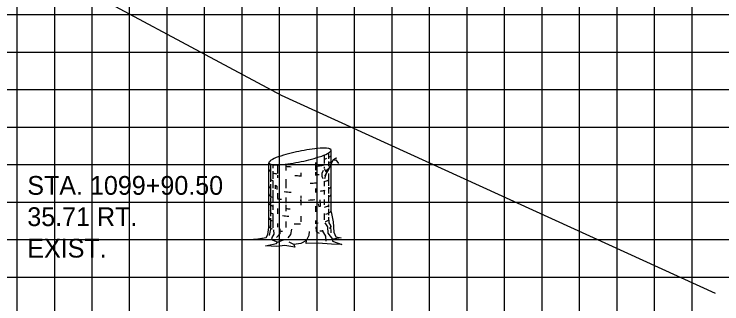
# Model space of a CAD drawing. Extents: x 1076304 to 1076474, y 779716 to 779826.
# Drawn here: x 1076415.71 to 1076434.59, y 779767.99 to 779775.71 of the extents above; entities that cross this region are included whole.
import ezdxf

# ---------------------------------------------------------------- set-up
doc = ezdxf.new("R2010")
doc.units = 0
for name, color, linetype in [('D_Text_Monospaced', 7, 'Continuous'), ('M_Trees_Conifer_Pay', 7, 'Continuous'), ('MAJOR', 7, 'Continuous'), ('MINOR', 7, 'Continuous'), ('S_Roadway_Centerline', 7, 'Continuous'), ('S_Trees_Decid_Pay', 7, 'Continuous')]:
    doc.layers.add(name, color=color, linetype=linetype)

msp = doc.modelspace()

# ---------------------------------------------------------------- linework, layer by layer
at = {"layer": 'M_Trees_Conifer_Pay'}
for p, q in [((1076424.171, 779770.443), (1076424.171, 779772.09)), ((1076423.982, 779771.957), (1076423.982, 779771.733)), ((1076424.099, 779772.018), (1076424.099, 779771.855)), ((1076422.507, 779770.033), (1076422.507, 779771.754)), ((1076422.554, 779771.717), (1076422.554, 779771.246)), ((1076422.613, 779771.706), (1076422.613, 779771.608)), ((1076422.958, 779771.718), (1076422.958, 779771.55)), ((1076423.754, 779771.76), (1076423.754, 779771.561)), ((1076424.099, 779771.787), (1076424.099, 779771.659)), ((1076422.613, 779771.534), (1076422.613, 779771.33)), ((1076422.738, 779771.698), (1076422.738, 779771.466)), ((1076423.982, 779771.645), (1076423.982, 779771.598)), ((1076422.738, 779771.425), (1076422.738, 779771.351)), ((1076423.363, 779771.487), (1076423.363, 779771.392)), ((1076423.754, 779771.503), (1076423.754, 779771.415)), ((1076424.039, 779771.462), (1076423.988, 779771.402)), ((1076424.099, 779771.472), (1076424.099, 779771.136)), ((1076422.554, 779771.182), (1076422.554, 779770.873)), ((1076422.613, 779771.272), (1076422.613, 779771.073)), ((1076422.958, 779771.314), (1076422.958, 779771.077)), ((1076423.982, 779771.262), (1076423.982, 779771.13)), ((1076422.613, 779771.025), (1076422.613, 779770.69)), ((1076423.754, 779771.067), (1076423.754, 779770.962)), ((1076423.982, 779771.02), (1076423.982, 779770.91)), ((1076424.099, 779771.1), (1076424.099, 779770.937)), ((1076422.554, 779770.826), (1076422.554, 779770.334)), ((1076422.738, 779770.947), (1076422.738, 779770.809)), ((1076422.958, 779770.832), (1076422.958, 779770.68)), ((1076423.363, 779770.873), (1076423.363, 779770.799)), ((1076423.363, 779770.774), (1076423.363, 779770.626)), ((1076423.982, 779770.774), (1076423.982, 779770.632)), ((1076424.099, 779770.89), (1076424.099, 779770.673)), ((1076422.613, 779770.636), (1076422.613, 779770.501)), ((1076422.958, 779770.636), (1076422.958, 779770.463)), ((1076423.754, 779770.595), (1076423.754, 779770.449)), ((1076424.099, 779770.642), (1076424.099, 779770.568)), ((1076422.613, 779770.401), (1076422.613, 779770.023)), ((1076422.738, 779770.537), (1076422.738, 779770.396)), ((1076423.982, 779770.405), (1076423.982, 779770.233)), ((1076424.099, 779770.527), (1076424.099, 779770.354)), ((1076422.554, 779770.28), (1076422.554, 779770.033)), ((1076423.363, 779770.334), (1076423.363, 779770.181)), ((1076423.754, 779770.216), (1076423.754, 779770.128)), ((1076422.738, 779770.134), (1076422.738, 779770.039)), ((1076422.958, 779770.186), (1076422.958, 779770.033)), ((1076422.738, 779769.64), (1076422.901, 779769.703)), ((1076423.175, 779769.575), (1076423.049, 779769.64))]:
    msp.add_line(p, q, dxfattribs=at)
for points in [[(1076423.988, 779771.588), (1076424.025, 779771.514), (1076424.072, 779771.571), (1076424.13, 779771.639), (1076424.222, 779771.833), (1076424.286, 779771.88), (1076424.317, 779771.886)], [(1076424.002, 779771.335), (1076424.039, 779771.462), (1076424.103, 779771.577), (1076424.134, 779771.645), (1076424.202, 779771.791)], [(1076424.217, 779771.821), (1076424.292, 779771.829), (1076424.365, 779771.73)], [(1076423.954, 779771.55), (1076423.924, 779771.466), (1076423.92, 779771.398), (1076423.951, 779771.335)], [(1076422.686, 779771.06), (1076422.68, 779771.155), (1076422.723, 779771.132), (1076422.723, 779771.038)], [(1076423.825, 779770.661), (1076423.838, 779770.585), (1076423.885, 779770.595), (1076423.872, 779770.762)], [(1076424.171, 779770.443), (1076424.222, 779770.181), (1076424.239, 779769.907), (1076424.296, 779769.782), (1076424.432, 779769.751), (1076424.202, 779769.714), (1076424.202, 779769.714), (1076424.208, 779769.667), (1076424.455, 779769.572), (1076424.181, 779769.588), (1076423.825, 779769.609), (1076423.504, 779769.598), (1076423.51, 779769.681), (1076423.362, 779769.598), (1076423.175, 779769.575), (1076423.199, 779769.508), (1076422.931, 779769.551), (1076422.711, 779769.524), (1076422.418, 779769.541), (1076422.707, 779769.598), (1076422.738, 779769.64), (1076422.575, 779769.697), (1076422.338, 779769.708), (1076422.098, 779769.708), (1076422.439, 779769.766), (1076422.481, 779769.846), (1076422.507, 779770.033)], [(1076424.097, 779770.3), (1076424.103, 779770.155), (1076424.15, 779770.086), (1076424.16, 779769.887)], [(1076423.761, 779770.05), (1076423.771, 779769.924), (1076423.846, 779769.88)], [(1076423.998, 779770.155), (1076424.072, 779770.05), (1076424.077, 779769.877), (1076424.202, 779769.714)], [(1076422.555, 779769.985), (1076422.534, 779769.907), (1076422.514, 779769.813)], [(1076422.633, 779769.965), (1076422.639, 779769.85), (1076422.586, 779769.761), (1076422.575, 779769.697)], [(1076422.796, 779769.992), (1076422.796, 779769.86), (1076422.707, 779769.761)], [(1076423.022, 779769.751), (1076423.09, 779769.846), (1076423.117, 779769.985)], [(1076423.51, 779769.681), (1076423.584, 779769.823), (1076423.594, 779769.924)], [(1076424.039, 779769.661), (1076424.025, 779769.798), (1076423.951, 779769.928)]]:
    msp.add_lwpolyline(points, dxfattribs=at)
for centre, radius, start, end in [((1076423.84, 779772.403), 0.571, 284.4317, 292.4132), ((1076423.339, 779775.766), 4.124, 264.6955, 266.7331), ((1076422.837, 779772.016), 0.571, 246.8597, 257.9846), ((1076423.338, 779775.534), 4.124, 275.7849, 277.0558), ((1076424.138, 779771.365), 0.0334, 343.9485, 354.2151), ((1076422.838, 779771.805), 0.571, 240, 247.0587), ((1076423.339, 779775.322), 4.124, 273.7052, 275.9504), ((1076423.84, 779771.805), 0.571, 284.4493, 297.0429), ((1076423.338, 779775.087), 4.124, 264.081, 266.6676), ((1076423.338, 779774.877), 4.124, 273.1493, 275.4569), ((1076423.338, 779774.877), 4.124, 270, 270.3581), ((1076423.839, 779771.122), 0.571, 285.3983, 297.1896), ((1076422.539, 779770.485), 0.0334, 163.9485, 180), ((1076422.826, 779770.931), 0.571, 241.2369, 248.0268), ((1076423.338, 779774.64), 4.124, 264.716, 266.3193), ((1076423.338, 779774.442), 4.124, 263.4991, 265.8397), ((1076423.839, 779770.729), 0.571, 288.5067, 297.2721), ((1076423.338, 779774.247), 4.124, 275.7849, 276.7896), ((1076423.338, 779774.026), 4.124, 262.4438, 263.512)]:
    msp.add_arc(centre, radius, start, end, dxfattribs=at)
at = {"layer": 'MAJOR'}
for p, q in [((1076416.794, 779754.706), (1076416.794, 779789.706)), ((1076421.794, 779754.706), (1076421.794, 779789.706)), ((1076426.794, 779754.706), (1076426.794, 779789.706)), ((1076431.794, 779754.706), (1076431.794, 779789.706)), ((1076316.794, 779774.706), (1076456.794, 779774.706)), ((1076316.794, 779769.706), (1076456.794, 779769.706))]:
    msp.add_line(p, q, dxfattribs=at)
at = {"layer": 'MINOR'}
for p, q in [((1076415.794, 779754.706), (1076415.794, 779789.706)), ((1076417.794, 779754.706), (1076417.794, 779789.706)), ((1076418.794, 779754.706), (1076418.794, 779789.706)), ((1076419.794, 779754.706), (1076419.794, 779789.706)), ((1076420.794, 779754.706), (1076420.794, 779789.706)), ((1076422.794, 779754.706), (1076422.794, 779789.706)), ((1076423.794, 779754.706), (1076423.794, 779789.706)), ((1076424.794, 779754.706), (1076424.794, 779789.706)), ((1076425.794, 779754.706), (1076425.794, 779789.706)), ((1076427.794, 779754.706), (1076427.794, 779789.706)), ((1076428.794, 779754.706), (1076428.794, 779789.706)), ((1076429.794, 779754.706), (1076429.794, 779789.706)), ((1076430.794, 779754.706), (1076430.794, 779789.706)), ((1076432.794, 779754.706), (1076432.794, 779789.706)), ((1076433.794, 779754.706), (1076433.794, 779789.706)), ((1076316.794, 779775.706), (1076456.794, 779775.706)), ((1076316.794, 779773.706), (1076456.794, 779773.706)), ((1076316.794, 779772.706), (1076456.794, 779772.706)), ((1076316.794, 779771.706), (1076456.794, 779771.706)), ((1076316.794, 779770.706), (1076456.794, 779770.706)), ((1076316.794, 779768.706), (1076456.794, 779768.706))]:
    msp.add_line(p, q, dxfattribs=at)
at = {"layer": 'S_Roadway_Centerline'}
msp.add_lwpolyline([(1076411.902, 779779.035), (1076416.122, 779777.151), (1076422.831, 779773.559), (1076434.412, 779768.283)], dxfattribs=at)
at = {"layer": 'S_Trees_Decid_Pay'}
for centre, radius, start, end in [((1076424.363, 779766.987), 5.179, 95.3794, 101.7194), ((1076423.952, 779771.345), 0.802, 79.2194, 95.3794), ((1076424.056, 779771.886), 0.251, 71.0501, 79.2194), ((1076424.11, 779772.046), 0.0817, 56.7194, 71.0501), ((1076424.126, 779772.07), 0.0527, 46.923, 56.7194), ((1076424.141, 779772.086), 0.0314, 34.2194, 46.923), ((1076424.145, 779772.088), 0.0264, 23.4074, 34.2194), ((1076424.148, 779772.09), 0.0226, 11.7194, 23.4074), ((1076424.14, 779772.091), 0.0314, 336.5158, 349.2194), ((1076424.148, 779772.09), 0.0226, 0.0315, 11.7194), ((1076424.145, 779772.09), 0.0264, 349.2194, 0.0315), ((1076423.006, 779771.148), 0.802, 108.0594, 124.2194), ((1076424.363, 779766.987), 5.179, 101.7194, 108.0594), ((1076422.315, 779776.857), 5.179, 281.7194, 288.0594), ((1076423.672, 779772.696), 0.802, 288.0594, 304.2194), ((1076423.982, 779772.24), 0.251, 304.2194, 312.3887), ((1076424.039, 779772.058), 0.172, 300, 311.2506), ((1076424.096, 779772.115), 0.0817, 312.3887, 326.7194), ((1076424.112, 779771.976), 0.0624, 311.2506, 330), ((1076424.12, 779772.099), 0.0527, 326.7194, 336.5158), ((1076424.128, 779771.967), 0.0441, 330, 343.9485), ((1076424.138, 779771.964), 0.0334, 343.9485, 354.2151), ((1076422.534, 779771.754), 0.0264, 169.2194, 180.0315), ((1076422.53, 779771.754), 0.0226, 180.0315, 191.7194), ((1076422.538, 779771.753), 0.0314, 156.5158, 169.2194), ((1076422.53, 779771.754), 0.0226, 191.7194, 203.4074), ((1076422.533, 779771.756), 0.0264, 203.4074, 214.2194), ((1076422.558, 779771.745), 0.0527, 146.7194, 156.5158), ((1076422.537, 779771.758), 0.0314, 214.2194, 226.923), ((1076422.582, 779771.729), 0.0817, 132.3887, 146.7194), ((1076422.552, 779771.774), 0.0527, 226.923, 236.7194), ((1076422.568, 779771.798), 0.0817, 236.7194, 251.0501), ((1076422.696, 779771.604), 0.251, 124.2194, 132.3887), ((1076422.623, 779771.958), 0.251, 251.0501, 259.2194), ((1076422.726, 779772.499), 0.802, 259.2194, 275.3794), ((1076422.315, 779776.857), 5.179, 275.3794, 281.7194), ((1076423.84, 779772.249), 0.571, 297.0237, 300), ((1076424.039, 779771.904), 0.172, 300, 311.2506), ((1076424.112, 779771.821), 0.0624, 311.2506, 330), ((1076424.128, 779771.812), 0.0441, 330, 343.9485), ((1076424.138, 779771.809), 0.0334, 343.9485, 354.2151), ((1076422.539, 779771.576), 0.0334, 163.9485, 180), ((1076422.539, 779771.576), 0.0334, 180, 196.0515), ((1076422.549, 779771.579), 0.0441, 196.0515, 210), ((1076422.565, 779771.588), 0.0624, 210, 228.7494), ((1076422.638, 779771.671), 0.172, 228.7494, 240), ((1076422.837, 779772.016), 0.571, 240, 240.3367), ((1076423.339, 779775.766), 4.124, 276.238, 278.1032), ((1076423.84, 779772.249), 0.571, 278.1032, 284.3667), ((1076423.338, 779775.534), 4.124, 268.0751, 270), ((1076423.338, 779775.534), 4.124, 270, 270.3581), ((1076422.539, 779771.129), 0.0334, 163.9485, 180), ((1076422.539, 779771.129), 0.0334, 180, 196.0515), ((1076422.549, 779771.132), 0.0441, 196.0515, 210), ((1076422.565, 779771.142), 0.0624, 210, 228.7494), ((1076422.638, 779771.224), 0.172, 228.7494, 240), ((1076422.837, 779771.569), 0.571, 240, 240.3367), ((1076423.338, 779775.087), 4.124, 277.6125, 278.1032), ((1076423.839, 779771.569), 0.571, 278.1032, 286.9296), ((1076423.839, 779771.569), 0.571, 297.1896, 300), ((1076424.038, 779771.224), 0.172, 300, 311.2506), ((1076424.11, 779771.142), 0.0624, 311.2506, 330), ((1076424.126, 779771.132), 0.0441, 330, 343.9485), ((1076424.136, 779771.129), 0.0334, 343.9485, 354.2151), ((1076422.539, 779770.919), 0.0334, 163.9485, 180), ((1076422.539, 779770.919), 0.0334, 180, 196.0515), ((1076422.549, 779770.922), 0.0441, 196.0515, 210), ((1076422.565, 779770.932), 0.0624, 210, 228.7494), ((1076422.638, 779771.014), 0.172, 228.7494, 240), ((1076422.837, 779771.359), 0.571, 240, 246.8597), ((1076422.837, 779771.359), 0.571, 259.2707, 261.8968), ((1076423.338, 779774.877), 4.124, 261.8968, 263.1474), ((1076423.839, 779771.359), 0.571, 297.1896, 300), ((1076424.038, 779771.014), 0.172, 300, 311.2506), ((1076424.11, 779770.932), 0.0624, 311.2506, 330), ((1076424.126, 779770.922), 0.0441, 330, 343.9485), ((1076424.136, 779770.919), 0.0334, 343.9485, 354.2151), ((1076422.539, 779770.683), 0.0334, 163.9485, 180), ((1076422.539, 779770.683), 0.0334, 180, 196.0515), ((1076422.549, 779770.686), 0.0441, 196.0515, 210), ((1076422.565, 779770.695), 0.0624, 210, 228.7494), ((1076422.638, 779770.777), 0.172, 228.7494, 240), ((1076422.837, 779771.122), 0.571, 240, 246.8597), ((1076423.839, 779770.925), 0.571, 289.2907, 300), ((1076424.038, 779770.58), 0.172, 300, 311.2506), ((1076424.11, 779770.497), 0.0624, 311.2506, 330), ((1076424.126, 779770.488), 0.0441, 330, 343.9485), ((1076424.136, 779770.485), 0.0334, 343.9485, 354.2151), ((1076422.539, 779770.289), 0.0334, 163.9485, 180), ((1076422.539, 779770.289), 0.0334, 180, 196.0515), ((1076422.549, 779770.292), 0.0441, 196.0515, 210), ((1076422.565, 779770.301), 0.0624, 210, 228.7494), ((1076422.638, 779770.384), 0.172, 228.7494, 240), ((1076422.837, 779770.729), 0.571, 240, 246.8597), ((1076422.539, 779770.069), 0.0334, 163.9485, 180), ((1076422.539, 779770.069), 0.0334, 180, 196.0515), ((1076422.549, 779770.072), 0.0441, 196.0515, 210), ((1076422.565, 779770.081), 0.0624, 210, 228.7494), ((1076422.638, 779770.164), 0.172, 228.7494, 240), ((1076422.837, 779770.509), 0.571, 240, 244.5314), ((1076423.338, 779774.247), 4.124, 267.8117, 270), ((1076423.338, 779774.247), 4.124, 270, 270.1328), ((1076424.038, 779770.164), 0.172, 300, 311.2506), ((1076424.11, 779770.081), 0.0624, 311.2506, 330), ((1076424.126, 779770.072), 0.0441, 330, 343.9485), ((1076424.136, 779770.069), 0.0334, 343.9485, 354.2151), ((1076423.338, 779774.026), 4.124, 277.3684, 278.1032), ((1076423.839, 779770.509), 0.571, 278.1032, 281.637)]:
    msp.add_arc(centre, radius, start, end, dxfattribs=at)

# ---------------------------------------------------------------- texts
at = {"layer": 'D_Text_Monospaced'}
for s, height, p in [('STA. 1099+90.50', 0.49998, (1076416.064, 779770.901)), ('35.71 RT.', 0.5, (1076416.064, 779770.067)), ('EXIST. ', 0.5, (1076416.064, 779769.227))]:
    msp.add_text(s, height=height, dxfattribs=at).set_placement(p)

doc.saveas('drawing.dxf')
